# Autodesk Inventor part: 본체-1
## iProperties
Created: 2015-05
Part Number: 본체-1
Material: 알루미늄-6061
Document SubType Name: Modeling
Designer: Win7
Mass: 1082.26 g
Surface Area: 1035.73 cm^2
Volume: 399.358 cm^3
Density: 2.71 g/cm^3
Author: Win7
